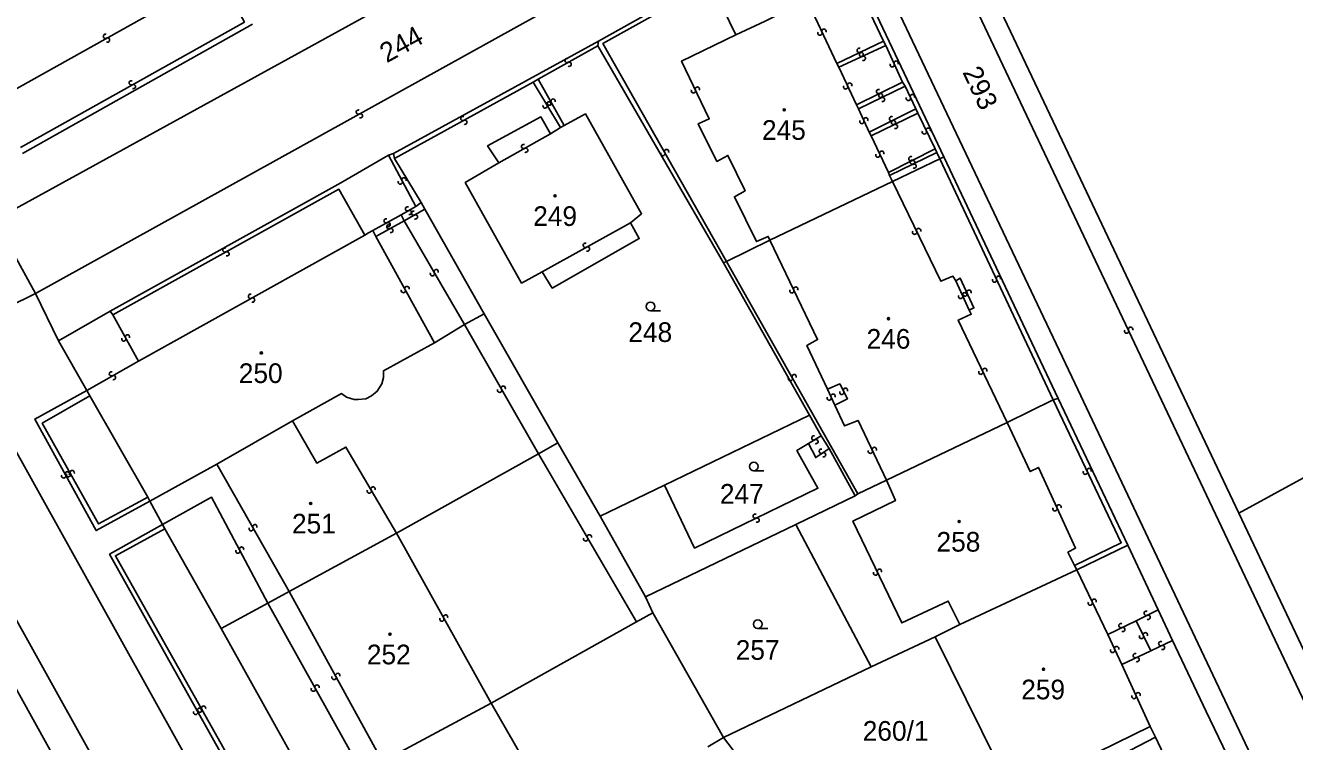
# Model space of a CAD drawing. Extents: x -600391 to -599491, y -1160176 to -1159402.
# Drawn here: x -600227.7 to -600117.8, y -1159912.4 to -1159850.4 of the extents above; entities that cross this region are included whole.
import ezdxf

# ---------------------------------------------------------------- set-up
doc = ezdxf.new("R2010")
doc.units = 0
for name, color, linetype in [('Level 1', 7, 'Continuous'), ('Level 13', 7, 'Continuous'), ('Level 3', 7, 'Continuous'), ('Level 4', 7, 'Continuous'), ('Level 5', 7, 'Continuous')]:
    doc.layers.add(name, color=color, linetype=linetype)

msp = doc.modelspace()

# ---------------------------------------------------------------- linework, layer by layer
at = {"layer": 'Level 1'}
for points in [[(-600122.68, -1159892.59), (-600149.28, -1159836.42)], [(-600158.21, -1159840.64), (-600178.06, -1159851.76)], [(-600148.19, -1159861.76), (-600158.21, -1159840.64)], [(-600227.9, -1159861.47), (-600208.01, -1159850.29)], [(-600178.06, -1159851.76), (-600195.8, -1159861.49)], [(-600178.06, -1159851.76), (-600178.12, -1159852.17)], [(-600178.12, -1159852.17), (-600167.26, -1159870.94)], [(-600186.69, -1159862.3), (-600187.67, -1159860.83), (-600183.06, -1159858.32), (-600182.22, -1159859.77)], [(-600181.05, -1159859.05), (-600179.2, -1159858.06), (-600174.34, -1159866.7), (-600175.29, -1159867.47)], [(-600182.22, -1159859.77), (-600181.35, -1159859.24)], [(-600181.35, -1159859.24), (-600181.05, -1159859.05)], [(-600196.25, -1159861.64), (-600200.37, -1159864.03), (-600220.32, -1159875.11)], [(-600195.8, -1159861.49), (-600196.25, -1159861.64)], [(-600195.8, -1159861.49), (-600195.72, -1159861.91)], [(-600148.55, -1159861.93), (-600148.19, -1159861.76)], [(-600138.31, -1159882.67), (-600148.19, -1159861.76)], [(-600122.68, -1159892.59), (-600066.1, -1159861.67)], [(-600195.72, -1159861.91), (-600193.41, -1159865.72)], [(-600182.95, -1159871.71), (-600184.72, -1159872.69), (-600189.6, -1159864), (-600186.69, -1159862.3)], [(-600152.64, -1159863.9), (-600148.55, -1159861.93)], [(-600163.24, -1159868.98), (-600152.64, -1159863.9)], [(-600193.41, -1159865.72), (-600193.11, -1159866.31)], [(-600226.79, -1159873.6), (-600230.31, -1159867.23)], [(-600193.11, -1159866.31), (-600187.97, -1159875.36)], [(-600175.29, -1159867.47), (-600174.54, -1159868.84), (-600182.08, -1159873.12), (-600182.95, -1159871.71)], [(-600166.99, -1159870.82), (-600163.24, -1159868.98)], [(-600167.26, -1159870.94), (-600166.99, -1159870.82)], [(-600167.26, -1159870.94), (-600159.83, -1159884.13)], [(-600224.8, -1159877.68), (-600226.79, -1159873.6)], [(-600220.32, -1159875.11), (-600224.8, -1159877.68)], [(-600189.67, -1159876.29), (-600187.97, -1159875.36)], [(-600187.97, -1159875.36), (-600181.6, -1159886.53)], [(-600192.26, -1159877.85), (-600189.67, -1159876.29)], [(-600224.8, -1159877.68), (-600222.35, -1159881.98)], [(-600204.54, -1159884.61), (-600200.32, -1159882.25), (-600199.86, -1159882.58), (-600199.2, -1159882.78), (-600198.86, -1159882.78), (-600198.2, -1159882.7), (-600197.7, -1159882.45), (-600197.22, -1159882.06), (-600196.81, -1159881.41), (-600196.67, -1159880.87), (-600196.67, -1159880.28), (-600192.26, -1159877.85)], [(-600222.35, -1159881.98), (-600222.08, -1159882.45)], [(-600222.08, -1159882.45), (-600217.05, -1159891.21)], [(-600138.73, -1159882.8), (-600138.31, -1159882.67)], [(-600132.27, -1159895.36), (-600138.31, -1159882.67)], [(-600142.71, -1159884.75), (-600138.73, -1159882.8)], [(-600211.09, -1159888.35), (-600204.54, -1159884.61)], [(-600159.83, -1159884.13), (-600172.36, -1159890.17)], [(-600159.83, -1159884.13), (-600158.8, -1159885.92)], [(-600153.15, -1159889.76), (-600142.71, -1159884.75)], [(-600158.8, -1159885.92), (-600158.12, -1159887.02)], [(-600183.26, -1159887.47), (-600181.6, -1159886.53)], [(-600181.6, -1159886.53), (-600177.93, -1159892.87)], [(-600158.12, -1159887.02), (-600155.86, -1159891.11)], [(-600195.55, -1159894.33), (-600183.26, -1159887.47)], [(-600216.89, -1159891.55), (-600211.09, -1159888.35)], [(-600172.36, -1159890.17), (-600177.93, -1159892.87)], [(-600155.63, -1159890.94), (-600153.15, -1159889.76)], [(-600217.05, -1159891.21), (-600216.89, -1159891.55)], [(-600161.01, -1159893.59), (-600155.86, -1159891.11)], [(-600155.86, -1159891.11), (-600155.63, -1159890.94)], [(-600216.89, -1159891.55), (-600215.8, -1159893.59)], [(-600215.8, -1159893.59), (-600215.59, -1159893.96)], [(-600177.93, -1159892.87), (-600174, -1159899.84)], [(-600174, -1159899.84), (-600161.01, -1159893.59)], [(-600154.49, -1159905.91), (-600161.01, -1159893.59)], [(-600094.36, -1159952.42), (-600122.68, -1159892.59)], [(-600215.59, -1159893.96), (-600210.72, -1159902.58)], [(-600204.82, -1159899.37), (-600195.55, -1159894.33)], [(-600136.7, -1159897.5), (-600132.27, -1159895.36)], [(-600129.64, -1159900.98), (-600132.27, -1159895.36)], [(-600146.82, -1159902.24), (-600136.7, -1159897.5)], [(-600206.67, -1159900.38), (-600204.82, -1159899.37)], [(-600173.38, -1159901.22), (-600174, -1159899.84)], [(-600210.72, -1159902.58), (-600206.67, -1159900.38)], [(-600174.78, -1159902.01), (-600173.38, -1159901.22)], [(-600167.26, -1159912.02), (-600173.38, -1159901.22)], [(-600128.41, -1159903.61), (-600129.64, -1159900.98)], [(-600187.37, -1159909.03), (-600174.78, -1159902.01)], [(-600148.94, -1159903.29), (-600146.82, -1159902.24)], [(-600210.72, -1159902.58), (-600202.47, -1159917.37)], [(-600154.49, -1159905.91), (-600148.94, -1159903.29)], [(-600148.94, -1159903.29), (-600142.24, -1159916.89), (-600130.34, -1159911.07)], [(-600123.72, -1159913.47), (-600125.51, -1159909.75), (-600128.41, -1159903.61)], [(-600229.06, -1159906.7), (-600224.75, -1159914.47)], [(-600167.26, -1159912.02), (-600154.49, -1159905.91)], [(-600196.76, -1159914.08), (-600187.37, -1159909.03)], [(-600130.34, -1159911.07), (-600129.88, -1159911.97)], [(-600168.6, -1159912.83), (-600167.26, -1159912.02)], [(-600167.26, -1159912.02), (-600161.59, -1159919.46)], [(-600129.88, -1159911.97), (-600143.7, -1159919.18), (-600147.73, -1159918.17), (-600151.08, -1159913.33), (-600155.83, -1159916.12)], [(-600129.88, -1159911.97), (-600128.22, -1159915.54)]]:
    msp.add_lwpolyline(points, dxfattribs=at)
at = {"layer": 'Level 13'}
for centre, start, end in [((-600158.57, -1159850.9), 332.6194, 204.7174), ((-600220.73, -1159851.34), 66.4071, 298.9971), ((-600220.55, -1159851.66), 246.6216, 118.7196), ((-600158.91, -1159851.06), 152.405, 24.995), ((-600155.52, -1159852.56), 62.9236, 295.5136), ((-600155.32, -1159852.91), 62.0496, 294.1476), ((-600155.36, -1159852.9), 243.1381, 115.2361), ((-600180.79, -1159853.44), 66.4556, 298.5536), ((-600180.61, -1159853.76), 246.2412, 118.8312), ((-600155.16, -1159853.25), 241.8351, 114.4251), ((-600152.66, -1159853.81), 151.5065, 24.0965), ((-600152.32, -1159853.66), 331.721, 203.819), ((-600218.49, -1159855.37), 66.3657, 298.9557), ((-600218.31, -1159855.69), 246.5802, 118.6782), ((-600169.86, -1159856.07), 152.9205, 25.0185), ((-600169.52, -1159855.91), 332.7061, 205.2961), ((-600156.69, -1159855.72), 152.1461, 24.7361), ((-600156.35, -1159855.56), 332.3606, 204.4586), ((-600153.84, -1159856.12), 63.4185, 295.5165), ((-600153.65, -1159856.47), 63.4822, 295.5802), ((-600153.68, -1159856.46), 243.204, 115.794), ((-600182.69, -1159857.37), 158.5296, 30.6275), ((-600182.37, -1159857.19), 338.3151, 210.9051), ((-600182.32, -1159857.13), 156.4516, 28.5496), ((-600182, -1159856.95), 336.2371, 208.8271), ((-600153.49, -1159856.81), 243.2677, 115.8577), ((-600151.26, -1159856.72), 152.1911, 24.7811), ((-600150.92, -1159856.56), 332.4055, 204.5035), ((-600198.85, -1159857.9), 66.3805, 298.4785), ((-600198.67, -1159858.22), 246.166, 118.756), ((-600189.81, -1159858.46), 66.1469, 298.2449), ((-600154.95, -1159858.56), 332.3275, 204.4255), ((-600152.72, -1159858.47), 64.1654, 296.2634), ((-600189.63, -1159858.78), 245.9324, 118.5224), ((-600155.29, -1159858.72), 152.113, 24.703), ((-600152.55, -1159858.81), 63.4799, 295.5779), ((-600152.56, -1159858.8), 243.9509, 116.5409), ((-600152.39, -1159859.15), 243.2654, 115.8554), ((-600149.88, -1159859.62), 153.1288, 25.7188), ((-600149.54, -1159859.46), 333.3433, 205.4413), ((-600184.55, -1159860.88), 66.8824, 298.9804), ((-600184.37, -1159861.2), 246.6679, 119.2579), ((-600172.5, -1159861.49), 156.7392, 29.3292), ((-600172.18, -1159861.31), 336.9537, 209.0517), ((-600153.91, -1159861.62), 152.403, 24.993), ((-600153.57, -1159861.46), 332.6175, 204.7155), ((-600151.05, -1159861.93), 64.0511, 296.1491), ((-600150.92, -1159862.23), 63.3181, 295.4161), ((-600150.89, -1159862.26), 243.8367, 116.4267), ((-600150.76, -1159862.57), 243.1036, 115.6936), ((-600195.22, -1159863.95), 155.5656, 27.6636), ((-600194.9, -1159863.77), 335.3512, 207.9412), ((-600194.59, -1159866.27), 66.4273, 298.5253), ((-600196.45, -1159867.31), 66.4866, 298.5846), ((-600194.41, -1159866.59), 246.2129, 118.8029), ((-600194.09, -1159866.65), 66.6999, 298.7979), ((-600193.91, -1159866.97), 246.4855, 119.0755), ((-600196.21, -1159867.82), 66.2284, 298.3264), ((-600196.27, -1159867.63), 246.2722, 118.8622), ((-600196.03, -1159868.14), 246.0139, 118.6039), ((-600150.72, -1159868.3), 152.922, 25.512), ((-600150.38, -1159868.14), 333.1365, 205.2345), ((-600179.21, -1159869.43), 66.1239, 298.7139), ((-600210.39, -1159869.84), 66.2328, 298.8228), ((-600210.21, -1159870.16), 246.4472, 118.5452), ((-600179.03, -1159869.75), 246.3384, 118.4363), ((-600192.12, -1159871.71), 337.3274, 209.9174), ((-600192.44, -1159871.89), 157.5418, 29.6398), ((-600143.81, -1159872.44), 152.3568, 24.9468), ((-600143.47, -1159872.28), 332.5712, 204.6692), ((-600208.18, -1159873.84), 66.4547, 298.5527), ((-600194.96, -1159873.34), 156.091, 28.681), ((-600194.64, -1159873.16), 336.3054, 208.4034), ((-600161.35, -1159873.37), 152.9445, 25.0425), ((-600161.01, -1159873.21), 332.73, 205.32), ((-600146.74, -1159873.85), 151.5172, 24.1072), ((-600146.4, -1159873.7), 331.7317, 203.8297), ((-600146.36, -1159873.64), 151.7202, 24.3102), ((-600146.02, -1159873.48), 331.9346, 204.0326), ((-600208, -1159874.16), 246.2402, 118.8302), ((-600218.82, -1159877.35), 335.9691, 208.5591), ((-600132.38, -1159876.85), 152.709, 24.807), ((-600132.04, -1159876.69), 332.4946, 205.0846), ((-600219.14, -1159877.53), 156.1835, 28.2815), ((-600220.21, -1159880.55), 66.9794, 299.0774), ((-600145, -1159880.41), 152.7572, 25.3472), ((-600144.66, -1159880.25), 332.9716, 205.0696), ((-600220.03, -1159880.87), 246.7649, 119.3549), ((-600161.47, -1159880.97), 156.8223, 28.9203), ((-600161.15, -1159880.79), 336.6079, 209.1979), ((-600186.63, -1159881.97), 156.9859, 29.5759), ((-600186.31, -1159881.79), 337.2003, 209.2983), ((-600158.12, -1159882.64), 152.4347, 24.5327), ((-600157.78, -1159882.48), 332.2203, 204.8103), ((-600157.02, -1159882.15), 155.3522, 27.4502), ((-600156.7, -1159881.97), 335.1378, 207.7278), ((-600159.44, -1159886.09), 67.952, 300.05), ((-600159.26, -1159886.41), 247.7375, 120.3275), ((-600158.8, -1159887.25), 70.9632, 303.5532), ((-600154.21, -1159887.09), 332.6517, 205.2417), ((-600158.6, -1159887.55), 251.1776, 123.2756), ((-600154.55, -1159887.25), 152.8661, 24.9641), ((-600224.02, -1159889.2), 336.2405, 208.3385), ((-600223.92, -1159889.27), 156.4191, 29.0091), ((-600223.6, -1159889.09), 336.6336, 208.7316), ((-600135.96, -1159889.06), 152.6, 25.19), ((-600135.62, -1159888.9), 332.8145, 204.9125), ((-600224.34, -1159889.38), 156.026, 28.616), ((-600197.58, -1159890.51), 337.7676, 209.8656), ((-600197.9, -1159890.69), 157.5532, 30.1432), ((-600138.58, -1159892.22), 151.923, 24.513), ((-600138.24, -1159892.06), 332.1375, 204.2355), ((-600207.8, -1159893.77), 336.7967, 209.3867), ((-600164.51, -1159892.86), 63.0536, 295.6436), ((-600164.35, -1159893.2), 243.2681, 115.3661), ((-600208.12, -1159893.95), 157.0111, 29.1091), ((-600179.18, -1159894.83), 157.4098, 29.9998), ((-600178.86, -1159894.65), 337.6243, 209.7223), ((-600209.27, -1159895.89), 155.4192, 27.5172), ((-600208.95, -1159895.71), 335.2048, 207.7948), ((-600154.11, -1159897.78), 153.0729, 25.1709), ((-600153.77, -1159897.62), 332.8585, 205.4485), ((-600135.19, -1159900.22), 332.9871, 205.0851), ((-600135.53, -1159900.38), 152.7726, 25.3626), ((-600130.68, -1159901.27), 63.2171, 295.3151), ((-600191.62, -1159901.77), 156.2526, 28.8426), ((-600191.3, -1159901.59), 336.467, 208.565), ((-600132.87, -1159902.33), 62.9986, 295.0966), ((-600130.52, -1159901.61), 243.0027, 115.5927), ((-600132.71, -1159902.67), 242.7841, 115.3741), ((-600131.1, -1159903.28), 153.2792, 25.8692), ((-600130.76, -1159903.12), 333.4936, 205.5916), ((-600133.59, -1159904.48), 151.9473, 24.5373), ((-600133.25, -1159904.32), 332.1617, 204.2597), ((-600129.43, -1159903.89), 62.7058, 294.8038), ((-600129.27, -1159904.23), 242.4914, 115.0814), ((-600131.63, -1159904.93), 63.0211, 295.1191), ((-600131.47, -1159905.27), 242.8067, 115.3967), ((-600200.95, -1159906.82), 156.0922, 28.1902), ((-600200.63, -1159906.64), 335.8778, 208.4678), ((-600202.74, -1159907.83), 156.4505, 28.5485), ((-600202.42, -1159907.65), 336.236, 208.826), ((-600131.74, -1159908.47), 151.8995, 24.4895), ((-600131.4, -1159908.31), 332.114, 204.212), ((-600212.92, -1159909.84), 156.3968, 28.9868), ((-600212.6, -1159909.66), 336.6113, 208.7093), ((-600212.56, -1159909.65), 156.5109, 29.1009), ((-600212.24, -1159909.47), 336.7254, 208.8234)]:
    msp.add_arc(centre, 0.184, start, end, dxfattribs=at)
at = {"layer": 'Level 3'}
for points in [[(-600230.31, -1159867.23), (-600164.72, -1159831.16), (-600163.95, -1159830.52), (-600163.4, -1159829.75)], [(-600058.2, -1160028.15), (-600058.36, -1160028.15), (-600059, -1160028.11), (-600059.48, -1160028.02), (-600059.94, -1160027.88), (-600060.54, -1160027.6), (-600093.98, -1159957.52), (-600113.29, -1159916.73), (-600151.13, -1159836.81), (-600151.44, -1159835.9), (-600151.54, -1159834.48), (-600151.24, -1159833.05), (-600151, -1159832.5)], [(-600268.81, -1159835), (-600268.21, -1159834.77), (-600267.62, -1159834.68), (-600267.01, -1159834.71), (-600266.39, -1159834.88), (-600265.88, -1159835.15), (-600265.47, -1159835.49), (-600265.11, -1159835.91), (-600218.12, -1159920.37), (-600217.94, -1159920.94), (-600217.91, -1159921.6), (-600218.02, -1159922.19), (-600218.24, -1159922.81), (-600218.57, -1159923.26), (-600218.96, -1159923.67), (-600219.39, -1159923.97)], [(-600226.79, -1159873.6), (-600170.72, -1159842.51), (-600161.99, -1159837.7), (-600160.92, -1159837.49), (-600159.66, -1159837.59)], [(-600159.66, -1159837.59), (-600159.21, -1159837.71), (-600158.35, -1159838.08), (-600157.61, -1159838.58), (-600157.12, -1159839.07), (-600156.56, -1159839.81), (-600136.86, -1159881.35), (-600099.49, -1159960.35), (-600082.51, -1159996.2), (-600082.35, -1159996.48), (-600082.21, -1159996.87), (-600082.15, -1159997.28), (-600082.21, -1159997.74), (-600082.31, -1159998.06), (-600082.48, -1159998.38), (-600082.79, -1159998.74), (-600083.08, -1159998.96), (-600083.18, -1159999.01)], [(-600162.48, -1159843.47), (-600158.42, -1159841.19), (-600153.42, -1159851.75)], [(-600210.89, -1159846.04), (-600230.39, -1159856.96)], [(-600210.89, -1159846.04), (-600208.7, -1159850.11), (-600228.09, -1159860.95)], [(-600168.36, -1159846.74), (-600177.69, -1159851.97), (-600166.99, -1159870.82)], [(-600166.2, -1159851.22), (-600168.36, -1159846.74)], [(-600166.2, -1159851.22), (-600163.64, -1159850.02), (-600160.31, -1159848.38)], [(-600160.03, -1159848.25), (-600157.46, -1159853.7)], [(-600163.24, -1159868.98), (-600163.38, -1159868.66), (-600164.39, -1159869.1), (-600166.31, -1159865.22), (-600165.39, -1159864.7), (-600166.87, -1159861.65), (-600167.83, -1159862.17), (-600169.44, -1159858.91), (-600168.49, -1159858.49), (-600170.88, -1159853.49), (-600166.2, -1159851.22)], [(-600153.42, -1159851.75), (-600157.46, -1159853.7)], [(-600153.42, -1159851.75), (-600153.2, -1159852.15)], [(-600183.28, -1159855.04), (-600178.12, -1159852.17)], [(-600157.27, -1159854.02), (-600153.2, -1159852.15)], [(-600153.2, -1159852.15), (-600151.77, -1159855.31)], [(-600157.46, -1159853.7), (-600157.27, -1159854.02)], [(-600157.27, -1159854.02), (-600155.76, -1159857.26)], [(-600183.72, -1159855.32), (-600183.28, -1159855.04)], [(-600181.05, -1159859.05), (-600183.28, -1159855.04)], [(-600195.72, -1159861.91), (-600183.72, -1159855.32)], [(-600181.35, -1159859.24), (-600183.72, -1159855.32)], [(-600155.76, -1159857.26), (-600151.77, -1159855.31)], [(-600155.59, -1159857.63), (-600151.55, -1159855.65)], [(-600151.77, -1159855.31), (-600151.55, -1159855.65)], [(-600151.55, -1159855.65), (-600150.63, -1159857.62)], [(-600155.76, -1159857.26), (-600155.59, -1159857.63)], [(-600155.59, -1159857.63), (-600154.65, -1159859.65)], [(-600154.65, -1159859.65), (-600150.63, -1159857.62)], [(-600154.48, -1159859.96), (-600150.46, -1159857.99)], [(-600150.63, -1159857.62), (-600150.46, -1159857.99)], [(-600150.46, -1159857.99), (-600148.95, -1159861.09)], [(-600186.69, -1159862.3), (-600182.22, -1159859.77)], [(-600154.65, -1159859.65), (-600154.48, -1159859.96)], [(-600154.48, -1159859.96), (-600152.99, -1159863.12)], [(-600193.87, -1159866.08), (-600196.25, -1159861.64)], [(-600152.99, -1159863.12), (-600148.95, -1159861.09)], [(-600152.89, -1159863.39), (-600148.8, -1159861.4)], [(-600148.95, -1159861.09), (-600148.8, -1159861.4)], [(-600148.8, -1159861.4), (-600148.55, -1159861.93)], [(-600148.55, -1159861.93), (-600138.73, -1159882.8)], [(-600152.99, -1159863.12), (-600152.89, -1159863.39)], [(-600152.89, -1159863.39), (-600152.64, -1159863.9)], [(-600152.64, -1159863.9), (-600148.47, -1159872.54), (-600147.41, -1159872.09), (-600147.15, -1159872.5)], [(-600198.3, -1159868.55), (-600200.53, -1159864.57), (-600220.08, -1159875.44)], [(-600195.13, -1159866.78), (-600193.87, -1159866.08)], [(-600193.87, -1159866.08), (-600193.41, -1159865.72)], [(-600197.59, -1159868.15), (-600195.13, -1159866.78)], [(-600194.89, -1159867.31), (-600195.13, -1159866.78)], [(-600194.89, -1159867.31), (-600193.11, -1159866.31)], [(-600198.3, -1159868.55), (-600197.98, -1159868.36), (-600197.59, -1159868.15)], [(-600197.59, -1159868.15), (-600197.34, -1159868.66)], [(-600197.34, -1159868.66), (-600194.89, -1159867.31)], [(-600189.67, -1159876.29), (-600194.89, -1159867.31)], [(-600175.29, -1159867.47), (-600182.95, -1159871.71)], [(-600217.88, -1159879.44), (-600198.3, -1159868.55)], [(-600197.34, -1159868.66), (-600192.26, -1159877.85)], [(-600158.27, -1159881.87), (-600160.05, -1159878.1), (-600159.12, -1159877.59), (-600163.24, -1159868.98)], [(-600155.63, -1159890.94), (-600166.99, -1159870.82)], [(-600147.15, -1159872.5), (-600146.77, -1159872.28), (-600145.6, -1159874.84), (-600146, -1159875.04)], [(-600147.15, -1159872.5), (-600146, -1159875.04)], [(-600226.79, -1159873.6), (-600229.16, -1159874.79), (-600229.52, -1159874.97), (-600230.51, -1159875.67), (-600231.28, -1159876.56), (-600231.76, -1159877.43), (-600232.13, -1159878.78), (-600232.17, -1159880), (-600231.89, -1159881.14), (-600211.75, -1159917.28), (-600210.89, -1159926.36), (-600152.6, -1160029.31), (-600151.79, -1160029.76)], [(-600220.08, -1159875.44), (-600220.32, -1159875.11)], [(-600217.88, -1159879.44), (-600220.08, -1159875.44)], [(-600146, -1159875.04), (-600145.82, -1159875.39), (-600146.95, -1159875.9), (-600142.71, -1159884.75)], [(-600189.67, -1159876.29), (-600183.26, -1159887.47)], [(-600222.35, -1159881.98), (-600217.88, -1159879.44)], [(-600157.62, -1159883.26), (-600156.52, -1159882.7), (-600157.2, -1159881.42), (-600158.27, -1159881.87)], [(-600222.35, -1159881.98), (-600226.84, -1159884.46), (-600221.52, -1159894.11), (-600216.89, -1159891.55)], [(-600222.08, -1159882.45), (-600226.2, -1159884.82), (-600221.32, -1159893.53), (-600217.05, -1159891.21)], [(-600157.62, -1159883.26), (-600158.27, -1159881.87)], [(-600153.15, -1159889.76), (-600155.62, -1159884.58), (-600156.78, -1159885.06), (-600157.62, -1159883.26)], [(-600138.73, -1159882.8), (-600132.85, -1159895.16), (-600136.89, -1159897.12)], [(-600204.54, -1159884.61), (-600202.45, -1159888.27), (-600199.92, -1159886.88), (-600195.55, -1159894.33)], [(-600142.71, -1159884.75), (-600140.72, -1159889), (-600140.02, -1159888.65), (-600136.8, -1159895.63), (-600137.46, -1159895.98), (-600136.89, -1159897.12)], [(-600159.9, -1159886.57), (-600158.8, -1159885.92)], [(-600159.9, -1159886.57), (-600160.91, -1159887.18), (-600159.09, -1159890.44), (-600169.76, -1159895.62), (-600172.36, -1159890.17)], [(-600158.12, -1159887.02), (-600159.27, -1159887.79), (-600159.9, -1159886.57)], [(-600183.26, -1159887.47), (-600174.78, -1159902.01)], [(-600204.82, -1159899.37), (-600211.09, -1159888.35)], [(-600146.82, -1159902.24), (-600147.81, -1159900.21), (-600151.82, -1159902.1), (-600156.06, -1159893.29), (-600152.39, -1159891.51), (-600153.15, -1159889.76)], [(-600206.67, -1159900.38), (-600211.55, -1159891.22), (-600215.8, -1159893.59)], [(-600215.8, -1159893.59), (-600220.37, -1159896.16), (-600205.15, -1159923.35), (-600200.41, -1159920.88)], [(-600215.59, -1159893.96), (-600219.86, -1159896.29), (-600204.94, -1159922.82), (-600200.62, -1159920.48)], [(-600195.55, -1159894.33), (-600187.37, -1159909.03)], [(-600136.89, -1159897.12), (-600136.7, -1159897.5)], [(-600136.7, -1159897.5), (-600134.02, -1159903.09)], [(-600196.76, -1159914.08), (-600204.82, -1159899.37)], [(-600198.49, -1159915.09), (-600206.67, -1159900.38)], [(-600131.56, -1159901.91), (-600129.64, -1159900.98)], [(-600134.02, -1159903.09), (-600131.56, -1159901.91)], [(-600131.56, -1159901.91), (-600130.29, -1159904.5)], [(-600134.02, -1159903.09), (-600132.81, -1159905.71)], [(-600132.81, -1159905.71), (-600130.29, -1159904.5)], [(-600130.29, -1159904.5), (-600128.41, -1159903.61)], [(-600132.81, -1159905.71), (-600130.34, -1159911.07)], [(-600187.37, -1159909.03), (-600183.16, -1159916.36), (-600185.64, -1159917.76), (-600183.6, -1159921.65)]]:
    msp.add_lwpolyline(points, dxfattribs=at)
at = {"layer": 'Level 5'}
for p, q in [((-600173.57, -1159875.09), (-600172.7, -1159875.09)), ((-600164.64, -1159888.95), (-600163.77, -1159888.95)), ((-600164.3, -1159902.59), (-600163.43, -1159902.59))]:
    msp.add_line(p, q, dxfattribs=at)
for centre, radius in [((-600162, -1159857.7), 0.09), ((-600162, -1159857.7), 0.0521), ((-600181.83, -1159865.15), 0.09), ((-600181.83, -1159865.15), 0.0521), ((-600173.57, -1159874.71), 0.375), ((-600152.99, -1159875.77), 0.09), ((-600152.99, -1159875.77), 0.0521), ((-600207.24, -1159878.74), 0.09), ((-600207.24, -1159878.74), 0.0521), ((-600164.64, -1159888.57), 0.375), ((-600202.97, -1159891.76), 0.09), ((-600202.97, -1159891.76), 0.0521), ((-600146.87, -1159893.33), 0.09), ((-600146.87, -1159893.33), 0.0521), ((-600164.3, -1159902.21), 0.375), ((-600196.11, -1159903.08), 0.09), ((-600196.11, -1159903.08), 0.0521), ((-600139.57, -1159906.11), 0.09), ((-600139.57, -1159906.11), 0.0521)]:
    msp.add_circle(centre, radius, dxfattribs=at)

# ---------------------------------------------------------------- texts
at = {"layer": 'Level 4'}
for s, rotation, p in [('244', 28.8, (-600196.39, -1159853.68)), ('293', 295.2, (-600146.61, -1159854.44))]:
    msp.add_text(s, height=1.7, rotation=rotation, dxfattribs=at).set_placement(p)
for s, p in [('245', (-600163.93, -1159860.3)), ('249', (-600183.72, -1159867.75)), ('248', (-600175.49, -1159877.79)), ('246', (-600154.88, -1159878.37)), ('250', (-600209.19, -1159881.34)), ('247', (-600167.57, -1159891.78)), ('251', (-600204.59, -1159894.36)), ('258', (-600148.83, -1159895.93)), ('252', (-600198.11, -1159905.68)), ('257', (-600166.2, -1159905.29)), ('259', (-600141.5, -1159908.71)), ('260/1', (-600155.21, -1159912.29))]:
    msp.add_text(s, height=1.7, dxfattribs=at).set_placement(p)

doc.saveas('drawing.dxf')
